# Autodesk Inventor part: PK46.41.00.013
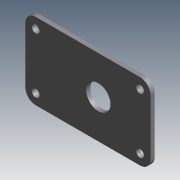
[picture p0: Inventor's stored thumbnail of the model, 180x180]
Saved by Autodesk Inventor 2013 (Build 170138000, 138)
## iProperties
Created: 2005-05
Part Number: PK46.41.00.013
Material: Steel, Mild
Document SubType Name: Листовой материал
Designer: PVitaliy
Manufacturer: Standard
Standards Organization: Custom
Density: 7.86 g/cm^3
Mass: 861.359 g
Surface Area: 413.438 cm^2
Volume: 109.588 cm^3
Author: PVitaliy
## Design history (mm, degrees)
node "ПК46.41.00.011" dims "d0" = 10
  node "РабПлоскость1"
body "Solid1"
tag "TaggingFeature2"
feature "DerivedBody::ПК46.41.00.011" dims "d0" = 10
